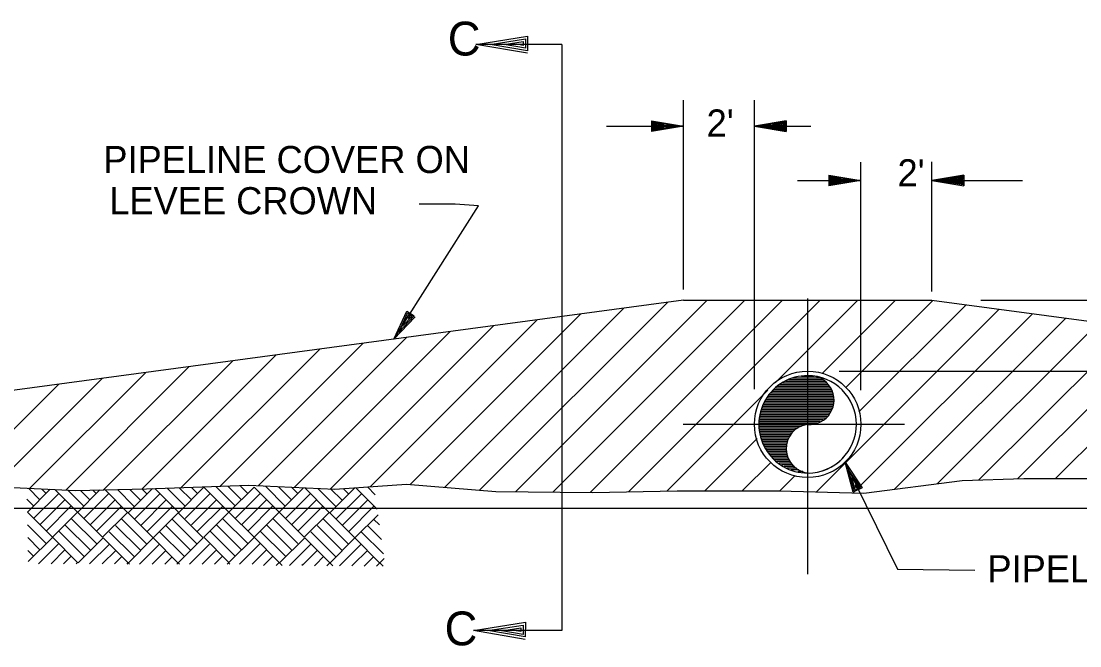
# Model space of a CAD drawing. Extents: x 2127959 to 2137375, y 2146193 to 2153470.
# Drawn here: x 2130315 to 2131601, y 2147106 to 2147865 of the extents above; entities that cross this region are included whole.
import ezdxf

# ---------------------------------------------------------------- set-up
doc = ezdxf.new("R2010")
doc.units = 0
for name, color, linetype in [('Level 1', 7, 'Continuous'), ('Level 3', 7, 'Continuous'), ('Level 5', 7, 'Continuous'), ('Level 50', 7, 'Continuous'), ('Level 63', 7, 'Continuous')]:
    doc.layers.add(name, color=color, linetype=linetype)

msp = doc.modelspace()

# ---------------------------------------------------------------- linework, layer by layer
at = {"layer": 'Level 1'}
for p, q in [((2131119.144, 2147525.847), (2129462.645, 2147303.347)), ((2131119.144, 2147525.847), (2131420.849, 2147525.847)), ((2131420.849, 2147525.847), (2133094.565, 2147302.516)), ((2129371.61, 2147272.911), (2133121.44, 2147272.911)), ((2131379.158, 2147198.867), (2131473.11, 2147197.6))]:
    msp.add_line(p, q, dxfattribs=at)
at = {"layer": 'Level 3'}
for p, q in [((2131119.144, 2147539.108), (2131119.144, 2147769.18)), ((2131205.347, 2147417.602), (2131205.347, 2147769.18)), ((2131080.408, 2147743.902), (2131080.408, 2147730.988)), ((2131080.408, 2147743.902), (2131119.144, 2147737.444)), ((2131081.165, 2147742.763), (2131081.115, 2147737.995)), ((2131113.423, 2147737.857), (2131081.979, 2147742.833)), ((2131081.979, 2147742.833), (2131081.979, 2147738.577)), ((2131244.106, 2147743.902), (2131205.347, 2147737.444)), ((2131243.309, 2147743.119), (2131211.899, 2147737.893)), ((2131243.362, 2147738.354), (2131243.309, 2147743.119)), ((2131244.106, 2147743.902), (2131244.106, 2147730.988)), ((2131025.809, 2147737.444), (2131119.144, 2147737.444)), ((2131119.144, 2147737.444), (2131080.408, 2147737.444)), ((2131119.144, 2147737.444), (2131080.408, 2147730.988)), ((2131080.956, 2147731.778), (2131113.37, 2147736.962)), ((2131081.131, 2147736.806), (2131080.956, 2147731.778)), ((2131081.115, 2147737.995), (2131113.423, 2147737.857)), ((2131081.925, 2147736.819), (2131081.907, 2147732.68)), ((2131081.907, 2147732.68), (2131105.957, 2147736.28)), ((2131113.37, 2147736.962), (2131081.925, 2147736.819)), ((2131081.979, 2147738.577), (2131106.163, 2147738.411)), ((2131105.957, 2147736.28), (2131082.738, 2147735.955)), ((2131082.738, 2147735.955), (2131082.817, 2147733.567)), ((2131106.163, 2147738.411), (2131082.817, 2147741.872)), ((2131082.817, 2147741.872), (2131082.817, 2147739.494)), ((2131082.817, 2147739.494), (2131095.319, 2147739.28)), ((2131082.817, 2147733.567), (2131095.495, 2147735.276)), ((2131095.495, 2147735.276), (2131083.715, 2147735.335)), ((2131083.715, 2147735.335), (2131083.735, 2147734.374)), ((2131083.735, 2147734.374), (2131087.323, 2147734.668)), ((2131095.319, 2147739.28), (2131083.754, 2147741.132)), ((2131083.754, 2147741.132), (2131083.788, 2147740.176)), ((2131083.788, 2147740.176), (2131087.442, 2147740.068)), ((2131205.347, 2147737.444), (2131274.014, 2147737.444)), ((2131205.347, 2147737.444), (2131244.106, 2147737.444)), ((2131205.347, 2147737.444), (2131244.106, 2147730.988)), ((2131211.899, 2147737.893), (2131242.688, 2147738.254)), ((2131243.482, 2147731.859), (2131212.002, 2147736.843)), ((2131212.002, 2147736.843), (2131242.639, 2147736.843)), ((2131242.639, 2147742.31), (2131218.139, 2147738.377)), ((2131218.139, 2147738.377), (2131241.778, 2147739.004)), ((2131242.725, 2147732.646), (2131218.297, 2147736.357)), ((2131218.297, 2147736.357), (2131241.862, 2147736.116)), ((2131241.689, 2147741.356), (2131227.395, 2147739.208)), ((2131227.395, 2147739.208), (2131240.982, 2147739.438)), ((2131241.844, 2147733.555), (2131227.587, 2147735.613)), ((2131227.587, 2147735.613), (2131241.087, 2147735.388)), ((2131241.256, 2147734.254), (2131236.933, 2147734.827)), ((2131241.035, 2147740.611), (2131236.947, 2147739.988)), ((2131240.982, 2147739.438), (2131241.035, 2147740.611)), ((2131241.087, 2147735.388), (2131241.256, 2147734.254)), ((2131241.778, 2147739.004), (2131241.689, 2147741.356)), ((2131241.862, 2147736.116), (2131241.844, 2147733.555)), ((2131242.688, 2147738.254), (2131242.639, 2147742.31)), ((2131242.639, 2147736.843), (2131242.725, 2147732.646)), ((2131243.413, 2147736.822), (2131243.482, 2147731.859)), ((2131334.649, 2147416.472), (2131334.649, 2147693.917)), ((2131420.849, 2147536.532), (2131420.849, 2147694.256)), ((2131257.552, 2147671.639), (2131334.649, 2147671.639)), ((2131295.909, 2147678.092), (2131295.909, 2147665.181)), ((2131295.909, 2147678.092), (2131334.649, 2147671.639)), ((2131334.649, 2147671.639), (2131295.909, 2147671.639)), ((2131334.649, 2147671.639), (2131295.909, 2147665.181)), ((2131296.46, 2147665.972), (2131328.874, 2147671.159)), ((2131296.632, 2147671.002), (2131296.46, 2147665.972)), ((2131296.67, 2147676.958), (2131296.619, 2147672.19)), ((2131296.619, 2147672.19), (2131328.926, 2147672.05)), ((2131297.425, 2147671.011), (2131297.413, 2147666.871)), ((2131297.413, 2147666.871), (2131321.459, 2147670.476)), ((2131328.874, 2147671.159), (2131297.425, 2147671.011)), ((2131328.926, 2147672.05), (2131297.48, 2147677.024)), ((2131297.48, 2147677.024), (2131297.48, 2147672.772)), ((2131297.48, 2147672.772), (2131321.668, 2147672.603)), ((2131321.459, 2147670.476), (2131298.237, 2147670.15)), ((2131298.237, 2147670.15), (2131298.324, 2147667.763)), ((2131321.668, 2147672.603), (2131298.324, 2147676.065)), ((2131298.324, 2147676.065), (2131298.324, 2147673.685)), ((2131298.324, 2147673.685), (2131310.821, 2147673.475)), ((2131298.324, 2147667.763), (2131310.995, 2147669.471)), ((2131310.995, 2147669.471), (2131299.22, 2147669.528)), ((2131299.22, 2147669.528), (2131299.24, 2147668.567)), ((2131299.24, 2147668.567), (2131302.823, 2147668.861)), ((2131310.821, 2147673.475), (2131299.252, 2147675.326)), ((2131299.252, 2147675.326), (2131299.291, 2147674.367)), ((2131299.291, 2147674.367), (2131302.945, 2147674.258)), ((2131459.605, 2147678.092), (2131420.849, 2147671.639)), ((2131420.849, 2147671.639), (2131530.959, 2147671.639)), ((2131420.849, 2147671.639), (2131459.605, 2147671.639)), ((2131420.849, 2147671.639), (2131459.605, 2147665.181)), ((2131458.813, 2147677.311), (2131427.403, 2147672.088)), ((2131427.403, 2147672.088), (2131458.191, 2147672.446)), ((2131458.983, 2147666.052), (2131427.506, 2147671.036)), ((2131427.506, 2147671.036), (2131458.14, 2147671.036)), ((2131458.14, 2147676.502), (2131433.641, 2147672.571)), ((2131433.641, 2147672.571), (2131457.28, 2147673.199)), ((2131458.227, 2147666.839), (2131433.798, 2147670.551)), ((2131433.798, 2147670.551), (2131457.365, 2147670.307)), ((2131457.193, 2147675.548), (2131442.9, 2147673.399)), ((2131442.9, 2147673.399), (2131456.485, 2147673.633)), ((2131457.347, 2147667.746), (2131443.09, 2147669.804)), ((2131443.09, 2147669.804), (2131456.59, 2147669.584)), ((2131456.759, 2147668.446), (2131452.433, 2147669.022)), ((2131456.538, 2147674.804), (2131452.451, 2147674.182)), ((2131456.485, 2147673.633), (2131456.538, 2147674.804)), ((2131456.59, 2147669.584), (2131456.759, 2147668.446)), ((2131457.28, 2147673.199), (2131457.193, 2147675.548)), ((2131457.365, 2147670.307), (2131457.347, 2147667.746)), ((2131458.191, 2147672.446), (2131458.14, 2147676.502)), ((2131458.14, 2147671.036), (2131458.227, 2147666.839)), ((2131458.865, 2147672.55), (2131458.813, 2147677.311)), ((2131458.915, 2147671.012), (2131458.983, 2147666.052)), ((2131459.605, 2147678.092), (2131459.605, 2147665.181)), ((2131269.999, 2147528.211), (2131269.999, 2147192.995)), ((2131480.569, 2147525.847), (2131959.901, 2147525.847)), ((2131308.441, 2147439.647), (2131954.262, 2147439.647)), ((2131295.219, 2147422.858), (2131235.964, 2147422.858)), ((2131293.755, 2147424.877), (2131239.553, 2147424.877)), ((2131290.945, 2147426.898), (2131243.153, 2147426.898)), ((2131288.15, 2147428.917), (2131246.758, 2147428.917)), ((2131285.341, 2147430.939), (2131250.74, 2147430.939)), ((2131277.961, 2147432.957), (2131262.483, 2147432.957)), ((2131301.149, 2147408.714), (2131221.932, 2147408.712)), ((2131300.857, 2147410.732), (2131223.693, 2147410.732)), ((2131300.565, 2147412.75), (2131225.45, 2147412.75)), ((2131300.136, 2147414.776), (2131227.208, 2147414.776)), ((2131298.909, 2147416.796), (2131228.982, 2147416.796)), ((2131297.666, 2147418.818), (2131230.741, 2147418.818)), ((2131296.447, 2147420.839), (2131232.5, 2147420.839)), ((2131300.394, 2147396.589), (2131215.743, 2147396.589)), ((2131300.909, 2147398.612), (2131216.537, 2147398.612)), ((2131301.427, 2147400.632), (2131217.347, 2147400.632)), ((2131301.962, 2147402.653), (2131218.139, 2147402.653)), ((2131301.756, 2147404.674), (2131218.935, 2147404.674)), ((2131301.444, 2147406.693), (2131220.156, 2147406.693)), ((2131292.136, 2147382.449), (2131211.83, 2147382.449)), ((2131293.688, 2147384.469), (2131211.899, 2147384.469)), ((2131295.238, 2147386.49), (2131211.971, 2147386.49)), ((2131296.791, 2147388.512), (2131212.554, 2147388.512)), ((2131298.324, 2147390.531), (2131213.346, 2147390.531)), ((2131299.339, 2147392.553), (2131214.159, 2147392.553)), ((2131299.859, 2147394.57), (2131214.948, 2147394.57)), ((2131118.7, 2147374.996), (2131387.819, 2147374.996)), ((2131258.379, 2147370.327), (2131211.415, 2147370.327)), ((2131262.069, 2147372.35), (2131211.487, 2147372.35)), ((2131267.359, 2147374.368), (2131211.554, 2147374.368)), ((2131281.756, 2147376.387), (2131211.621, 2147376.387)), ((2131285.323, 2147378.406), (2131211.69, 2147378.406)), ((2131288.877, 2147380.426), (2131211.758, 2147380.426)), ((2131254.689, 2147368.306), (2131211.348, 2147368.306)), ((2131254.689, 2147368.306), (2131211.348, 2147368.306)), ((2131252.948, 2147366.287), (2131211.499, 2147366.287)), ((2131251.362, 2147364.265), (2131212.142, 2147364.265)), ((2131249.76, 2147362.245), (2131212.777, 2147362.245)), ((2131248.155, 2147360.228), (2131213.414, 2147360.228)), ((2131246.917, 2147358.205), (2131214.052, 2147358.205)), ((2131246.343, 2147356.185), (2131214.69, 2147356.185)), ((2131245.794, 2147354.166), (2131215.346, 2147354.166)), ((2131245.226, 2147352.145), (2131215.983, 2147352.145)), ((2131244.673, 2147350.125), (2131216.622, 2147350.125)), ((2131244.106, 2147348.104), (2131217.26, 2147348.104)), ((2131244.155, 2147346.081), (2131218.642, 2147346.081)), ((2131244.413, 2147344.063), (2131220.156, 2147344.063)), ((2131244.673, 2147342.041), (2131221.69, 2147342.041)), ((2131244.947, 2147340.022), (2131223.225, 2147340.022)), ((2131244.947, 2147340.022), (2131223.225, 2147340.022)), ((2131245.206, 2147338.002), (2131224.76, 2147338.002)), ((2131245.465, 2147335.982), (2131226.296, 2147335.982)), ((2131246.587, 2147333.964), (2131227.828, 2147333.964)), ((2131247.778, 2147331.94), (2131229.345, 2147331.94)), ((2131248.948, 2147329.92), (2131232.241, 2147329.92)), ((2131250.138, 2147327.899), (2131235.309, 2147327.899)), ((2131251.328, 2147325.882), (2131238.399, 2147325.882)), ((2131253.843, 2147323.862), (2131241.484, 2147323.862)), ((2131256.55, 2147321.841), (2131244.553, 2147321.841)), ((2131259.254, 2147319.82), (2131249.76, 2147319.82)), ((2131264.155, 2147317.797), (2131258.05, 2147317.797)), ((2131264.155, 2147317.797), (2131258.05, 2147317.797))]:
    msp.add_line(p, q, dxfattribs=at)
for points in [[(2130767.221, 2147478.575), (2130870.077, 2147640.612), (2130841.944, 2147642.864), (2130798.15, 2147642.864)], [(2131315.285, 2147328.851), (2131379.158, 2147198.867)]]:
    msp.add_lwpolyline(points, dxfattribs=at)
msp.add_circle((2131269.998, 2147374.995), 64.651, dxfattribs=at)
for centre, radius, start, end in [((2131269.998, 2147374.995), 59.263, 89.967033, 270.067694), ((2131272.462, 2147404.46), 29.593, 265.223189, 93.671583), ((2131269.998, 2147374.995), 59.263, 270.067731, 89.966992), ((2131273.587, 2147345.458), 29.706, 96.837989, 267.666692), ((2131269.995, 2147375.02), 59.288, 270.002506, 317.100794)]:
    msp.add_arc(centre, radius, start, end, dxfattribs=at)
at = {"layer": 'Level 5'}
for p, q in [((2130915.264, 2147293.085), (2131148.026, 2147525.847)), ((2130960.553, 2147292.653), (2131193.743, 2147525.847)), ((2131005.843, 2147292.225), (2131239.447, 2147525.847)), ((2131052.358, 2147293.029), (2131285.169, 2147525.847)), ((2131230.761, 2147425.724), (2131330.893, 2147525.847)), ((2131287.755, 2147436.996), (2131376.595, 2147525.847)), ((2131315.89, 2147419.417), (2131422.143, 2147525.677)), ((2130829.164, 2147298.41), (2131046.896, 2147516.14)), ((2130871.405, 2147294.932), (2131099.699, 2147523.232)), ((2131280.823, 2147292.919), (2131502.808, 2147514.913)), ((2131332.183, 2147389.997), (2131462.487, 2147520.292)), ((2130738.447, 2147299.129), (2130941.279, 2147501.951)), ((2130786.927, 2147301.885), (2130994.088, 2147509.047)), ((2131325.322, 2147291.712), (2131543.153, 2147509.53)), ((2131375.474, 2147296.142), (2131583.477, 2147504.148)), ((2131427.918, 2147302.868), (2131623.818, 2147498.766)), ((2130646.234, 2147298.346), (2130835.664, 2147487.768)), ((2130689.968, 2147296.353), (2130888.473, 2147494.86)), ((2131478.14, 2147307.381), (2131664.145, 2147493.383)), ((2131525.448, 2147308.965), (2131704.468, 2147488.002)), ((2130556.042, 2147299.58), (2130730.034, 2147473.582)), ((2130602.506, 2147300.334), (2130782.84, 2147480.674)), ((2131571.321, 2147309.125), (2131744.812, 2147482.62)), ((2130508.622, 2147297.88), (2130677.227, 2147466.49)), ((2130414.514, 2147295.2), (2130571.615, 2147452.303)), ((2130461.288, 2147296.255), (2130624.426, 2147459.396)), ((2130325.08, 2147297.195), (2130465.999, 2147438.117)), ((2130368.619, 2147295.02), (2130518.809, 2147445.208)), ((2130236.642, 2147300.191), (2130360.385, 2147423.929)), ((2130281.191, 2147299.02), (2130413.193, 2147431.023)), ((2131098.958, 2147293.919), (2131221.605, 2147416.566)), ((2131144.904, 2147294.151), (2131208.572, 2147357.807)), ((2131190.626, 2147294.151), (2131225.155, 2147328.692)), ((2131236.313, 2147294.128), (2131255.051, 2147312.858)), ((2131338.217, 2147291.365), (2131457.779, 2147306.699)), ((2131457.779, 2147306.699), (2131532.704, 2147309.209)), ((2131532.704, 2147309.209), (2131663.763, 2147308.929)), ((2130296.744, 2147298.615), (2130380.398, 2147294.43)), ((2130322.049, 2147268.087), (2130349.918, 2147295.954)), ((2130337.291, 2147283.331), (2130323.341, 2147297.283)), ((2130339.416, 2147296.474), (2130344.929, 2147290.966)), ((2130383.002, 2147268.087), (2130355.412, 2147295.679)), ((2130390.481, 2147275.556), (2130371.14, 2147294.891)), ((2130380.398, 2147294.43), (2130466.839, 2147296.379)), ((2130410.121, 2147295.195), (2130382.879, 2147267.953)), ((2130386.59, 2147294.726), (2130398.119, 2147283.192)), ((2130401.515, 2147295.025), (2130405.73, 2147290.802)), ((2130443.881, 2147267.953), (2130416.512, 2147295.323)), ((2130451.483, 2147275.556), (2130431.417, 2147295.62)), ((2130473.959, 2147296.82), (2130444.492, 2147267.353)), ((2130446.383, 2147295.928), (2130459.118, 2147283.192)), ((2130461.132, 2147296.403), (2130466.731, 2147290.802)), ((2130466.839, 2147296.379), (2130591.274, 2147300.843)), ((2130477.105, 2147296.926), (2130506.056, 2147267.975)), ((2130513.705, 2147275.573), (2130491.878, 2147297.399)), ((2130536.58, 2147298.449), (2130506.105, 2147267.975)), ((2130521.293, 2147283.209), (2130506.631, 2147297.876)), ((2130521.419, 2147298.359), (2130528.957, 2147290.824)), ((2130536.58, 2147298.449), (2130567.054, 2147267.975)), ((2130574.554, 2147275.727), (2130550.885, 2147299.399)), ((2130582.165, 2147283.339), (2130565.658, 2147299.853)), ((2130566.926, 2147268.097), (2130597.4, 2147298.571)), ((2130581.119, 2147299.661), (2130589.806, 2147290.976)), ((2130591.274, 2147300.843), (2130695.486, 2147296.102)), ((2130627.88, 2147268.097), (2130597.4, 2147298.571)), ((2130635.353, 2147275.565), (2130611.638, 2147299.283)), ((2130627.103, 2147299.096), (2130642.993, 2147283.202)), ((2130657.616, 2147297.828), (2130627.753, 2147267.962)), ((2130642.926, 2147298.49), (2130650.604, 2147290.816)), ((2130688.763, 2147267.962), (2130658.953, 2147297.764)), ((2130696.362, 2147275.565), (2130674.885, 2147297.041)), ((2130719.846, 2147297.837), (2130689.365, 2147267.365)), ((2130690.886, 2147296.312), (2130703.999, 2147283.202)), ((2130695.486, 2147296.102), (2130782.635, 2147302.238)), ((2130705.572, 2147296.858), (2130711.606, 2147290.816)), ((2130720.984, 2147297.928), (2130747.188, 2147271.718)), ((2130744.795, 2147289.375), (2130735.256, 2147298.913)), ((2130782.635, 2147302.238), (2130891.023, 2147293.314)), ((2130891.023, 2147293.314), (2131008.481, 2147292.199)), ((2131008.481, 2147292.199), (2131111.32, 2147294.151)), ((2131111.32, 2147294.151), (2131235.396, 2147294.151)), ((2131235.396, 2147294.151), (2131338.217, 2147291.365)), ((2130329.68, 2147275.716), (2130321.51, 2147283.885)), ((2130329.649, 2147260.484), (2130360.154, 2147290.986)), ((2130367.765, 2147283.322), (2130337.29, 2147252.849)), ((2130390.631, 2147260.455), (2130420.979, 2147290.802)), ((2130398.245, 2147252.845), (2130428.595, 2147283.192)), ((2130452.093, 2147259.701), (2130482.592, 2147290.207)), ((2130459.731, 2147252.114), (2130490.207, 2147282.591)), ((2130513.705, 2147260.323), (2130544.204, 2147290.824)), ((2130521.344, 2147252.73), (2130551.816, 2147283.209)), ((2130574.524, 2147260.495), (2130605.025, 2147290.997)), ((2130612.637, 2147283.336), (2130582.161, 2147252.855)), ((2130635.505, 2147260.466), (2130665.857, 2147290.816)), ((2130643.119, 2147252.851), (2130673.47, 2147283.202)), ((2130696.964, 2147259.712), (2130727.466, 2147290.216)), ((2130704.603, 2147252.126), (2130735.087, 2147282.602)), ((2130352.525, 2147237.608), (2130322.049, 2147268.087)), ((2130375.4, 2147275.737), (2130344.902, 2147245.233)), ((2130352.525, 2147237.608), (2130383.002, 2147268.087)), ((2130383.002, 2147268.087), (2130413.479, 2147237.608)), ((2130436.233, 2147275.556), (2130405.885, 2147245.204)), ((2130443.834, 2147267.953), (2130413.488, 2147237.604)), ((2130474.969, 2147236.826), (2130444.492, 2147267.302)), ((2130497.841, 2147274.956), (2130467.343, 2147244.452)), ((2130505.444, 2147267.353), (2130474.969, 2147236.875)), ((2130505.444, 2147267.302), (2130535.795, 2147236.955)), ((2130559.454, 2147275.573), (2130528.957, 2147245.071)), ((2130536.447, 2147237.62), (2130566.93, 2147268.102)), ((2130597.4, 2147237.62), (2130566.926, 2147268.097)), ((2130620.273, 2147275.744), (2130589.774, 2147245.245)), ((2130597.4, 2147237.62), (2130627.88, 2147268.097)), ((2130627.88, 2147268.097), (2130658.355, 2147237.62)), ((2130681.109, 2147275.565), (2130650.759, 2147245.217)), ((2130688.707, 2147267.962), (2130658.358, 2147237.613)), ((2130719.846, 2147236.841), (2130689.365, 2147267.316)), ((2130742.723, 2147274.962), (2130712.226, 2147244.464)), ((2130375.4, 2147260.484), (2130405.903, 2147229.982)), ((2130436.842, 2147259.701), (2130467.343, 2147229.202)), ((2130497.841, 2147259.701), (2130528.193, 2147229.357)), ((2130559.274, 2147260.495), (2130589.774, 2147229.995)), ((2130620.273, 2147260.495), (2130650.776, 2147229.995)), ((2130681.706, 2147259.712), (2130712.226, 2147229.214)), ((2130748.084, 2147265.132), (2130719.846, 2147236.888)), ((2130742.723, 2147259.712), (2130749.791, 2147252.649)), ((2130322.134, 2147252.752), (2130344.902, 2147229.982)), ((2130390.653, 2147214.733), (2130360.153, 2147245.233)), ((2130398.241, 2147222.375), (2130367.765, 2147252.849)), ((2130452.093, 2147213.954), (2130421.591, 2147244.452)), ((2130429.255, 2147252.067), (2130459.731, 2147221.592)), ((2130512.943, 2147214.106), (2130482.592, 2147244.452)), ((2130520.553, 2147221.72), (2130490.207, 2147252.067)), ((2130574.524, 2147214.742), (2130544.024, 2147245.245)), ((2130551.683, 2147252.855), (2130582.161, 2147222.379)), ((2130635.527, 2147214.742), (2130605.025, 2147245.245)), ((2130643.114, 2147222.379), (2130612.637, 2147252.855)), ((2130696.964, 2147213.962), (2130666.463, 2147244.464)), ((2130674.123, 2147252.076), (2130704.603, 2147221.6)), ((2130754.583, 2147217.342), (2130727.466, 2147244.464)), ((2130752.189, 2147234.964), (2130735.087, 2147252.076)), ((2130322.449, 2147237.206), (2130337.29, 2147222.375)), ((2130323.035, 2147208.068), (2130352.525, 2147237.561)), ((2130335.57, 2147205.403), (2130360.153, 2147229.982)), ((2130352.525, 2147237.608), (2130383.002, 2147207.135)), ((2130383.661, 2147206.485), (2130414.14, 2147236.958)), ((2130397.633, 2147205.249), (2130421.764, 2147229.387)), ((2130444.612, 2147206.485), (2130414.14, 2147236.958)), ((2130414.14, 2147236.958), (2130444.612, 2147206.485)), ((2130474.969, 2147236.826), (2130444.492, 2147206.351)), ((2130458.493, 2147205.1), (2130482.592, 2147229.202)), ((2130474.969, 2147236.826), (2130505.444, 2147206.351)), ((2130505.312, 2147206.473), (2130535.791, 2147236.952)), ((2130518.987, 2147204.955), (2130543.412, 2147229.374)), ((2130566.926, 2147207.141), (2130536.447, 2147237.62)), ((2130566.926, 2147207.095), (2130597.4, 2147237.571)), ((2130579.839, 2147204.805), (2130605.025, 2147229.995)), ((2130597.4, 2147237.62), (2130627.88, 2147207.141)), ((2130628.535, 2147206.495), (2130659.01, 2147236.973)), ((2130641.897, 2147204.655), (2130666.639, 2147229.394)), ((2130689.484, 2147206.495), (2130659.01, 2147236.973)), ((2130659.01, 2147236.973), (2130689.484, 2147206.495)), ((2130719.846, 2147236.841), (2130689.365, 2147206.361)), ((2130702.761, 2147204.505), (2130727.466, 2147229.214)), ((2130719.846, 2147236.841), (2130750.324, 2147206.361)), ((2130329.649, 2147214.735), (2130322.765, 2147221.621)), ((2130367.765, 2147222.322), (2130350.808, 2147205.366)), ((2130429.377, 2147221.725), (2130412.866, 2147205.216)), ((2130473.687, 2147205.064), (2130490.207, 2147221.592)), ((2130551.027, 2147221.714), (2130534.23, 2147204.919)), ((2130612.637, 2147222.333), (2130595.076, 2147204.769)), ((2130674.247, 2147221.732), (2130657.138, 2147204.623)), ((2130717.95, 2147204.469), (2130735.087, 2147221.6)), ((2130375.4, 2147214.735), (2130365.998, 2147205.328)), ((2130381.211, 2147205.288), (2130383.002, 2147207.083)), ((2130437.014, 2147214.136), (2130428.056, 2147205.176)), ((2130443.271, 2147205.136), (2130444.612, 2147206.485)), ((2130444.612, 2147206.485), (2130445.966, 2147205.134)), ((2130497.841, 2147213.954), (2130488.921, 2147205.029)), ((2130503.829, 2147204.992), (2130505.312, 2147206.473)), ((2130506.803, 2147204.984), (2130505.312, 2147206.473)), ((2130558.665, 2147214.121), (2130549.426, 2147204.879)), ((2130564.635, 2147204.841), (2130566.264, 2147206.473)), ((2130567.952, 2147204.834), (2130566.315, 2147206.473)), ((2130610.262, 2147204.733), (2130609.017, 2147203.489)), ((2130620.273, 2147214.742), (2130610.262, 2147204.733)), ((2130624.166, 2147203.387), (2130625.477, 2147204.693)), ((2130625.477, 2147204.693), (2130627.88, 2147207.095)), ((2130628.485, 2147206.495), (2130630.295, 2147204.686)), ((2130630.295, 2147204.686), (2130631.644, 2147203.333)), ((2130640.517, 2147203.272), (2130641.897, 2147204.655)), ((2130657.138, 2147204.623), (2130655.692, 2147203.17)), ((2130672.329, 2147204.578), (2130670.813, 2147203.067)), ((2130681.882, 2147214.143), (2130672.329, 2147204.578)), ((2130685.97, 2147202.967), (2130687.537, 2147204.544)), ((2130687.537, 2147204.544), (2130689.484, 2147206.495)), ((2130689.484, 2147206.495), (2130691.451, 2147204.532)), ((2130691.451, 2147204.532), (2130693.051, 2147202.915)), ((2130701.122, 2147202.862), (2130702.761, 2147204.505)), ((2130716.243, 2147202.761), (2130717.95, 2147204.469)), ((2130733.189, 2147204.433), (2130731.412, 2147202.654)), ((2130742.723, 2147213.962), (2130733.189, 2147204.433)), ((2130746.26, 2147202.555), (2130748.102, 2147204.396)), ((2130748.102, 2147204.396), (2130750.188, 2147206.485)), ((2130750.188, 2147206.485), (2130755.361, 2147211.667)), ((2130752.273, 2147204.384), (2130750.188, 2147206.485)), ((2130754.169, 2147202.501), (2130752.273, 2147204.384))]:
    msp.add_line(p, q, dxfattribs=at)
at = {"layer": 'Level 50'}
for p, q in [((2130866.974, 2147837.054), (2130866.974, 2147837.054)), ((2130884.441, 2147836.915), (2130884.441, 2147836.915)), ((2130773.158, 2147487.203), (2130773.158, 2147487.203)), ((2130767.344, 2147478.709), (2130767.344, 2147478.709)), ((2131315.411, 2147328.795), (2131315.411, 2147328.795)), ((2131319.683, 2147319.437), (2131319.683, 2147319.437)), ((2130864.18, 2147124.336), (2130864.18, 2147124.336)), ((2130881.645, 2147124.199), (2130881.645, 2147124.199))]:
    msp.add_line(p, q, dxfattribs=at)
for points in [[(2130929.715, 2147826.192), (2130866.974, 2147837.054), (2130929.842, 2147847.018), (2130929.719, 2147829.225), (2130884.441, 2147836.915), (2130927.119, 2147843.674), (2130927.058, 2147832.249), (2130901.23, 2147836.792), (2130924.419, 2147840.333), (2130924.393, 2147835.642), (2130918.698, 2147836.68)], [(2130793.299, 2147505.763), (2130767.344, 2147478.709), (2130783.168, 2147512.669), (2130791.826, 2147506.761), (2130773.158, 2147487.203), (2130783.913, 2147510.249), (2130789.473, 2147506.453), (2130778.752, 2147495.338), (2130784.646, 2147507.843), (2130786.94, 2147506.266), (2130784.548, 2147503.833)], [(2131325.225, 2147292.614), (2131315.411, 2147328.795), (2131336.373, 2147297.737), (2131326.848, 2147293.359), (2131319.683, 2147319.437), (2131333.911, 2147298.348), (2131327.795, 2147295.538), (2131323.781, 2147310.448), (2131331.467, 2147298.958), (2131328.939, 2147297.802), (2131328.087, 2147301.098)], [(2130926.921, 2147113.476), (2130864.18, 2147124.336), (2130927.047, 2147134.301), (2130926.924, 2147116.508), (2130881.645, 2147124.199), (2130924.325, 2147130.956), (2130924.263, 2147119.532), (2130898.436, 2147124.076), (2130921.624, 2147127.616), (2130921.599, 2147122.925), (2130915.904, 2147123.962)]]:
    msp.add_lwpolyline(points, dxfattribs=at)
at = {"layer": 'Level 63'}
for p, q in [((2130971.191, 2147837.054), (2130866.974, 2147837.054)), ((2130971.191, 2147837.054), (2130971.191, 2147124.336)), ((2130971.191, 2147124.336), (2130864.18, 2147124.336))]:
    msp.add_line(p, q, dxfattribs=at)

# ---------------------------------------------------------------- texts
at = {"layer": 'Level 1'}
for s, p in [("2'", (2131147.274, 2147724.947)), ('PIPELINE COVER ON ', (2130414.334, 2147680.588)), ("2'", (2131379.218, 2147664.407)), ('LEVEE CROWN', (2130421.532, 2147630.486)), ('PIPELINE', (2131488.379, 2147182.916))]:
    msp.add_text(s, height=32.931, dxfattribs=at).set_placement(p)
at = {"layer": 'Level 63'}
for p in [(2130832.812, 2147823.489), (2130828.979, 2147106.214)]:
    msp.add_text('C', height=41.164, dxfattribs=at).set_placement(p)

doc.saveas('drawing.dxf')
